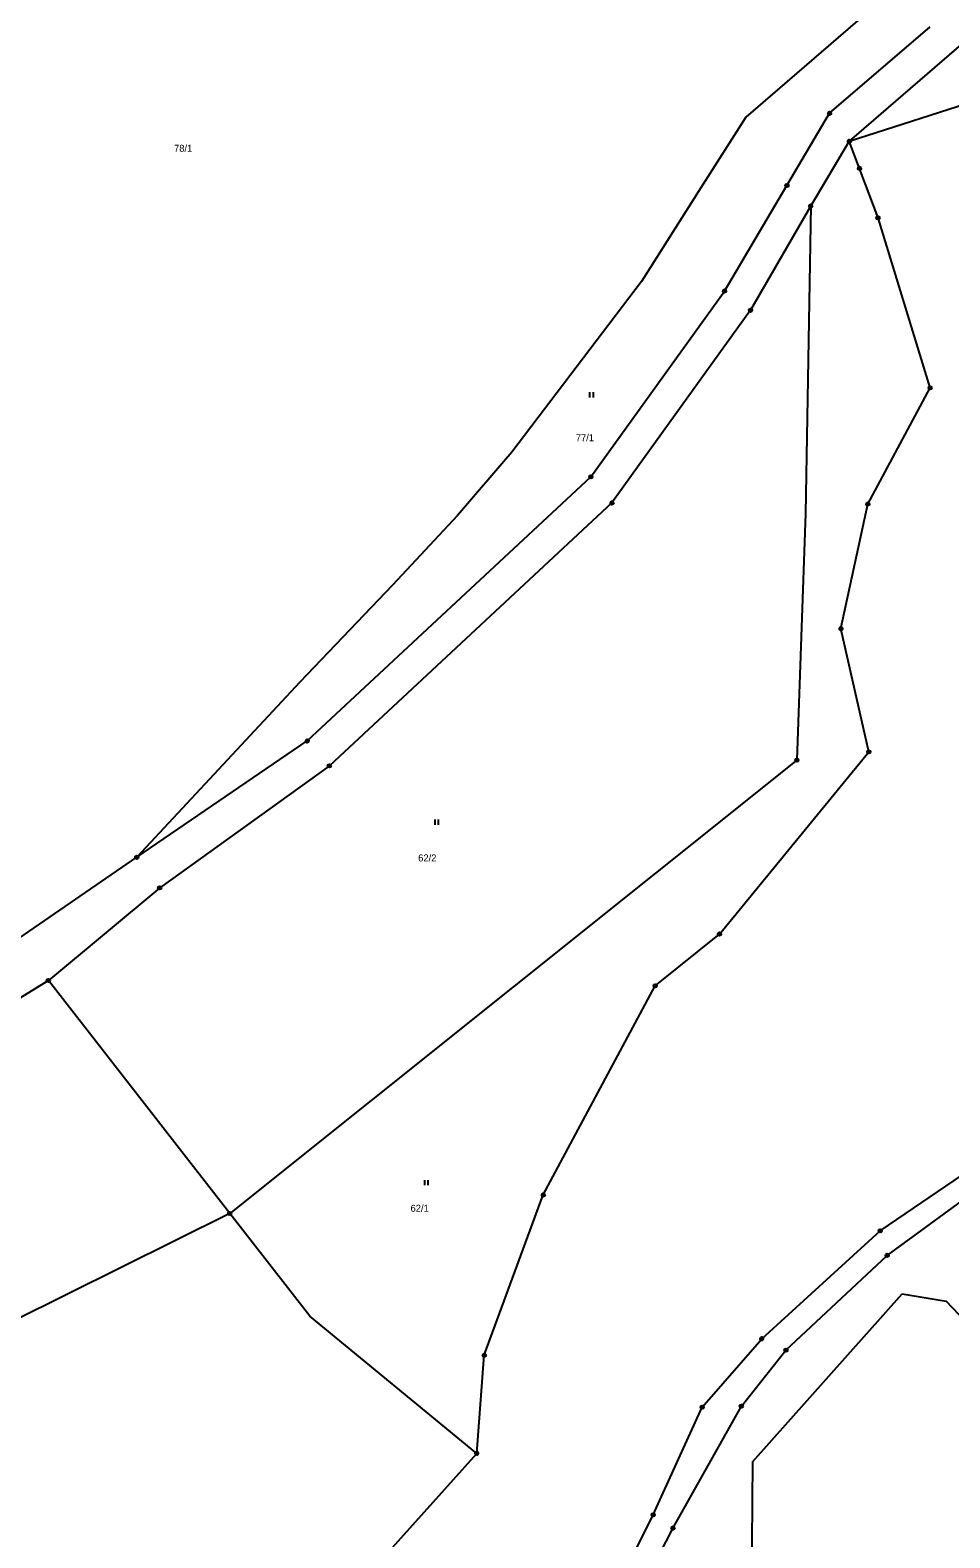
# Model space of a CAD drawing. Extents: x -745926 to -742978, y -968282 to -965689.
# Drawn here: x -743757.5 to -743626.1, y -967371.6 to -967156.2 of the extents above; entities that cross this region are included whole.
import ezdxf

# ---------------------------------------------------------------- set-up
doc = ezdxf.new("R2010")
doc.units = 0
for name, color, linetype in [('Hranice parcel', 7, 'Continuous'), ('Parcelní čísla', 7, 'Continuous'), ('Značky bodu BP', 7, 'Continuous'), ('Značky kultur', 7, 'Continuous')]:
    doc.layers.add(name, color=color, linetype=linetype)

msp = doc.modelspace()

# ---------------------------------------------------------------- linework, layer by layer
at = {"layer": 'Hranice parcel'}
for p, q in [((-743643.3, -967168.09), (-743628.94, -967155.71)), ((-743640.49, -967172.08), (-743614.79, -967163.77)), ((-743640.49, -967172.08), (-743646.01, -967181.32)), ((-743646.01, -967181.32), (-743646.75, -967225.26)), ((-743759.88, -967286.47), (-743742.28, -967274.4)), ((-743729.02, -967325.29), (-743754.93, -967292)), ((-743654.29, -967360.72), (-743632.93, -967336.77))]:
    msp.add_line(p, q, dxfattribs=at)
for points in [[(-743582.53, -967115.35), (-743596.26, -967133.82), (-743640.49, -967172.08)], [(-743632.36, -967148.83), (-743655.29, -967168.65), (-743661.72, -967178.73), (-743670.18, -967192.12), (-743688.73, -967216.51), (-743696.45, -967225.57), (-743705.76, -967235.53), (-743719.01, -967249.38), (-743742.28, -967274.4)], [(-743742.28, -967274.4), (-743717.94, -967257.77), (-743677.41, -967220.04), (-743658.32, -967193.48), (-743649.4, -967178.41), (-743643.3, -967168.09)], [(-743693.73, -967359.57), (-743692.64, -967345.56), (-743684.22, -967322.65), (-743668.22, -967292.77), (-743659.04, -967285.37), (-743637.7, -967259.34), (-743641.69, -967241.72), (-743637.85, -967223.92), (-743628.95, -967207.32), (-743636.39, -967183.03), (-743639.04, -967175.95), (-743640.49, -967172.08)], [(-743646.01, -967181.32), (-743654.61, -967196.23), (-743674.4, -967223.76), (-743714.78, -967261.32), (-743739.02, -967278.76), (-743754.93, -967292)], [(-743688.56, -967400.76), (-743676.45, -967384.29), (-743668.51, -967368.35), (-743661.51, -967352.98), (-743653, -967343.19), (-743636.09, -967327.77), (-743608.98, -967309.34), (-743604.68, -967301.37), (-743595.3, -967285.25), (-743589.41, -967270.86), (-743583.21, -967255.26), (-743556.54, -967227.96), (-743532.63, -967203.09)], [(-743674.65, -967387.78), (-743665.68, -967370.23), (-743655.91, -967352.83), (-743649.54, -967344.83), (-743635.08, -967331.28), (-743606.4, -967310.35), (-743601.3, -967303), (-743593.02, -967288.42), (-743585.41, -967270.8), (-743579.68, -967256.65), (-743554.03, -967229.92), (-743530.13, -967204.81)], [(-743632.93, -967336.77), (-743626.65, -967337.83), (-743620.47, -967344.34), (-743605.07, -967340.97), (-743590.67, -967333.41), (-743579.28, -967315.49), (-743575.59, -967306.36), (-743577.33, -967301.01), (-743581.94, -967279.31), (-743580.11, -967266.41), (-743570.62, -967258.21), (-743552, -967248.2), (-743541.92, -967238.96), (-743533.35, -967221.17)], [(-743646.75, -967225.26), (-743647.99, -967260.52), (-743729.02, -967325.29)], [(-743754.93, -967292), (-743773.22, -967303.26), (-743791.24, -967301.66), (-743799.74, -967295.65), (-743805.97, -967291.84)], [(-743729.02, -967325.29), (-743767.76, -967344.54), (-743812.45, -967348.17), (-743845.36, -967366.25), (-743888.51, -967392.58), (-743911.25, -967370.05), (-743940.62, -967331.53), (-743939.65, -967315.12)], [(-743693.73, -967359.57), (-743717.59, -967339.97), (-743729.02, -967325.29)], [(-743809.98, -967393.1), (-743771.19, -967393.38), (-743743.14, -967385.65), (-743720.77, -967389.76), (-743693.73, -967359.57)], [(-743674.65, -967387.78), (-743654.42, -967378.15), (-743654.29, -967360.72)]]:
    msp.add_lwpolyline(points, dxfattribs=at)
at = {"layer": 'Značky bodu BP'}
for centre, radius in [((-743643.3, -967168.09), 0.25), ((-743643.3, -967168.09), 0.0152), ((-743640.49, -967172.08), 0.25), ((-743640.49, -967172.08), 0.0152), ((-743639.04, -967175.95), 0.25), ((-743639.04, -967175.95), 0.0152), ((-743649.4, -967178.41), 0.25), ((-743649.4, -967178.41), 0.0152), ((-743646.01, -967181.32), 0.25), ((-743646.01, -967181.32), 0.0152), ((-743636.39, -967183.03), 0.25), ((-743636.39, -967183.03), 0.0152), ((-743658.32, -967193.48), 0.25), ((-743658.32, -967193.48), 0.0152), ((-743654.61, -967196.23), 0.25), ((-743654.61, -967196.23), 0.0152), ((-743628.95, -967207.32), 0.25), ((-743628.95, -967207.32), 0.0152), ((-743677.41, -967220.04), 0.25), ((-743677.41, -967220.04), 0.0152), ((-743674.4, -967223.76), 0.25), ((-743674.4, -967223.76), 0.0152), ((-743637.85, -967223.92), 0.25), ((-743637.85, -967223.92), 0.0152), ((-743641.69, -967241.72), 0.25), ((-743641.69, -967241.72), 0.0152), ((-743717.94, -967257.77), 0.25), ((-743717.94, -967257.77), 0.0152), ((-743647.99, -967260.52), 0.25), ((-743647.99, -967260.52), 0.0152), ((-743637.7, -967259.34), 0.25), ((-743637.7, -967259.34), 0.0152), ((-743714.78, -967261.32), 0.25), ((-743714.78, -967261.32), 0.0152), ((-743742.28, -967274.4), 0.25), ((-743742.28, -967274.4), 0.0152), ((-743739.02, -967278.76), 0.25), ((-743739.02, -967278.76), 0.0152), ((-743659.04, -967285.37), 0.25), ((-743659.04, -967285.37), 0.0152), ((-743754.93, -967292), 0.25), ((-743754.93, -967292), 0.0152), ((-743668.22, -967292.77), 0.25), ((-743668.22, -967292.77), 0.0152), ((-743684.22, -967322.65), 0.25), ((-743684.22, -967322.65), 0.0152), ((-743729.02, -967325.29), 0.25), ((-743729.02, -967325.29), 0.0152), ((-743636.09, -967327.77), 0.25), ((-743636.09, -967327.77), 0.0152), ((-743635.08, -967331.28), 0.25), ((-743635.08, -967331.28), 0.0152), ((-743653, -967343.19), 0.25), ((-743653, -967343.19), 0.0152), ((-743649.54, -967344.83), 0.25), ((-743649.54, -967344.83), 0.0152), ((-743692.64, -967345.56), 0.25), ((-743692.64, -967345.56), 0.0152), ((-743661.51, -967352.98), 0.25), ((-743661.51, -967352.98), 0.0152), ((-743655.91, -967352.83), 0.25), ((-743655.91, -967352.83), 0.0152), ((-743693.73, -967359.57), 0.25), ((-743693.73, -967359.57), 0.0152), ((-743668.51, -967368.35), 0.25), ((-743668.51, -967368.35), 0.0152), ((-743665.68, -967370.23), 0.25), ((-743665.68, -967370.23), 0.0152)]:
    msp.add_circle(centre, radius, dxfattribs=at)
at = {"layer": 'Značky kultur'}
for p, q in [((-743677.55, -967208.69), (-743677.55, -967207.94)), ((-743677.05, -967208.69), (-743677.05, -967207.94)), ((-743699.67, -967269.77), (-743699.67, -967269.02)), ((-743699.17, -967269.77), (-743699.17, -967269.02)), ((-743701.16, -967321.27), (-743701.16, -967320.52)), ((-743700.66, -967321.27), (-743700.66, -967320.52))]:
    msp.add_line(p, q, dxfattribs=at)

# ---------------------------------------------------------------- texts
at = {"layer": 'Parcelní čísla'}
for s, p in [('78/1', (-743736.97, -967173.58)), ('77/1', (-743679.57, -967214.94)), ('62/2', (-743702.09, -967274.99)), ('62/1', (-743703.18, -967325.05))]:
    msp.add_text(s, height=1, dxfattribs=at).set_placement(p)

doc.saveas('drawing.dxf')
